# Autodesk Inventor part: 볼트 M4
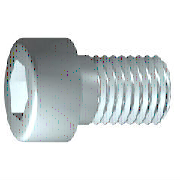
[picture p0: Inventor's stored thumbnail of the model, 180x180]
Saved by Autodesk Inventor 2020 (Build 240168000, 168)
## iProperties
Created: 2012-02
Part Number: 볼트 M4
Material: 스테인리스강
Description: 6각 소켓 머리 캡 나사
Document SubType Name: Modeling
Standard: ISO 4762
Designer: mduedu
Standard Revision: Fourth edition 2004-03-01
Standards Organization: ISO
Language: ko-KR
Size Designation: M4 x 12
Categories: <MemberInstance><Categories><Category DisplayName="조임쇠" InternalName="e4da775c-781d-43d5-af7c-5136215cf5a6" Mnemonic="FSTN"><Category DisplayName="볼트" InternalN
Density: 7.75 g/cm^3
Appearance: 반광택
IsCustomPart: 0
Author: mduedu
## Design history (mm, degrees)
sketch "스케치1"
  geometry: L1 (-1, 0)-(12, 0); L2 (12, 0)-(12, 2); L3 (12, 2)-(1.75, 2); L4 (1.75, 2)-(1.32, 2); L5 (1.32, 2)-(0, 2); L6 (0, 2)-(0, 3.5); L7 (0, 3.5)-(-4, 3.5); L8 (-4, 3.5)-(-4, 1.732); L9 (-4, 1.732)-(-2, 1.732); L10 (-2, 1.732)-(-1, 0); L11 (-7.2, 0)-(15.2, 0) reference; L12 (0, -0.7)-(0, 4.2) reference; L13 (1.75, 2)-(0, 2)
  constraints: 22 end point, 6 parallel, 2 collinear, 2 perpendicular, 1 horizontal, 1 point on line
  dimensions: "d1" = 10.25 distance from line of L3.end L2 (= GEL); "d2" = 0.42952 distance of L4.end L3.end (computed from GAL); "d3" = 4 distance between parallel lines of L8 L6 (= KOH); "d4" = 2 distance of L8.end L9.end (= INTI); "d5" = 60 deg angle of L10 L1; "d6" = 4 diameter of L3 L1 (= GD); "d7" = 4 diameter of L5 L1 (= BDM); "d8" = 3.4641 diameter of L9 L1 (= 1.1547 x SW); "d9" = 7 diameter of L7 L1 (= KOD); "d26" = 12 distance between parallel lines of L12 L2 (= NLG)
revolve "본체" sketch "스케치1" stored, may be unused: angle "d10" = 90 deg
sketch "스케치2"
  geometry: L1 (0, -4.9)-(0, 4.9) reference; L2 (-4.9, 0)-(4.9, 0) reference; L3 (1.732, 0)-(0.866, -1.5); L4 (0.866, -1.5)-(-0.866, -1.5); L5 (-0.866, -1.5)-(-1.732, 0); L6 (-1.732, 0)-(-0.866, 1.5); L7 (-0.866, 1.5)-(0.866, 1.5); L8 (0.866, 1.5)-(1.732, 0); 2 further points
  constraints: 12 end point, 1 coincident, 1 horizontal alignment, 1 point on line, 12 other
extrude "슬롯" join sketch "스케치2" stored distance "d11" = 10; taper "d12" = 0 deg
workplane "Work Plane1"
fillet "Fillet2" dims "d30" = 0.1 (= R)
body "Solid1"
fillet "모깎기1" dims "d17" = 0.4 (= RR)
feature "스레드" dims "d13" = 10.25 (= GEL), "d14" = 0
chamfer "모따기1" distance "d15" = 0.42941 (= -0.5 x SPD + 0.5 x GD); stored, may be unused: second distance "d16" = 0.42941 (= GUL), angle "d27" = 45 deg
other parameters: "GD" = 4 [user parameter; used in 2 equation terms], "NLG" = 12 [user parameter; used in 1 equation term], "GEL" = 10.25 [user parameter; used in 2 equation terms], "KOD" = 7 [user parameter; used in 1 equation term], "KOH" = 4 [user parameter; used in 1 equation term], "INTI" = 2 [user parameter; used in 1 equation term], "GAL" = 0.42941 (= 0.61345 x PTC) [user parameter; used in 1 equation term], "GUL" = 0.42941 (= 0.61345 x PTC) [user parameter; used in 1 equation term], "BDM" = 4 (= NND) [user parameter; used in 1 equation term], "SW" = 3 [user parameter; used in 2 equation terms], "RR" = 0.4 [user parameter; used in 1 equation term], "SPD" = 3.14117 (= NND - 1.2269 x PTC) [user parameter; used in 1 equation term], "d19" = 0, "d28" = 0, "d29" = 0, "R" = 0.1 [user parameter; used in 1 equation term], "TOA" = 30 deg [user parameter], "GD1" = 3.14117 (= THREADDIA - 1.2269 x PTC) [user parameter], "THREADDIA" = 4 [user parameter; used in 1 equation term], "FAWI" = 45 deg [user parameter], "TPU" = 14.28571 (computed from PTC) [user parameter], "PTC" = 0.7 [user parameter; used in 5 equation terms], "NND" = 4 [user parameter; used in 2 equation terms], "E0" = 3.465 (= 1.155 x SW) [user parameter]
